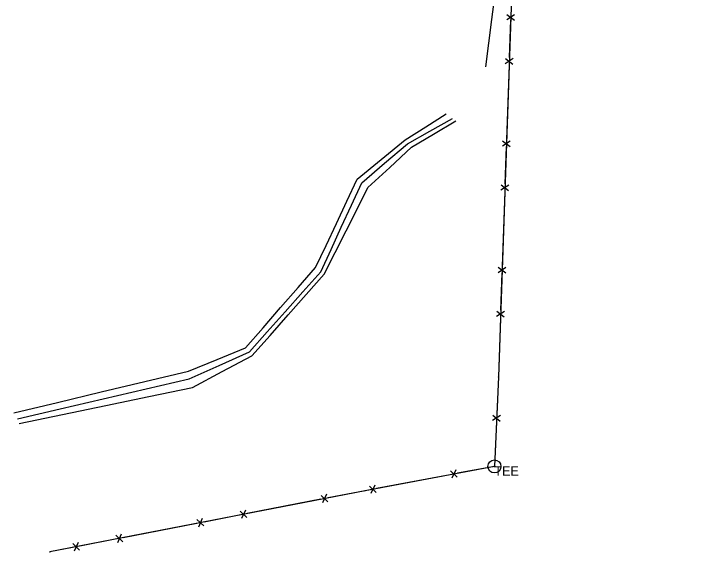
# Model space of a CAD drawing. Extents: x 675481 to 678499, y 212715 to 215285.
# Drawn here: x 676284.7 to 676656.9, y 214248.1 to 214534.9 of the extents above; entities that cross this region are included whole.
import ezdxf

# ---------------------------------------------------------------- set-up
doc = ezdxf.new("R2010")
doc.units = 0
for name, color, linetype in [('S_FENCE', 7, 'Continuous'), ('S_FENCE_ANNOT', 7, 'Continuous'), ('S_MSC_PT_SYM', 7, 'Continuous'), ('S_STREAM', 7, 'Continuous')]:
    doc.layers.add(name, color=color, linetype=linetype)

msp = doc.modelspace()

# ---------------------------------------------------------------- linework, layer by layer
at = {"layer": 'S_FENCE'}
for p, q in [((676554.13, 214666.5), (676542.97, 214341.43)), ((676551.65, 214534.51), (676547.46, 214531.78)), ((676547.55, 214534.65), (676551.55, 214531.64)), ((676550.84, 214511.09), (676546.65, 214508.36)), ((676546.75, 214511.23), (676550.75, 214508.22)), ((676549.33, 214467.11), (676545.14, 214464.39)), ((676545.24, 214467.25), (676549.23, 214464.25)), ((676548.53, 214443.69), (676544.34, 214440.97)), ((676544.44, 214443.83), (676548.43, 214440.83)), ((676547.02, 214399.72), (676542.83, 214396.99)), ((676542.92, 214399.86), (676546.92, 214396.85)), ((676546.21, 214376.3), (676542.02, 214373.57)), ((676542.12, 214376.44), (676546.12, 214373.43)), ((676542.97, 214341.43), (676540.86, 214293.75)), ((676544.11, 214320.8), (676539.89, 214318.12)), ((676540.01, 214320.98), (676543.98, 214317.94)), ((676540.86, 214293.75), (676471.89, 214280.77)), ((676521.03, 214287.93), (676517.45, 214291.43)), ((676520.27, 214291.96), (676518.21, 214287.4)), ((676477.79, 214279.79), (676474.21, 214283.29)), ((676477.03, 214283.82), (676474.97, 214279.26)), ((676471.89, 214280.77), (676303.89, 214248.15)), ((676452.09, 214274.84), (676448.49, 214278.31)), ((676451.31, 214278.86), (676449.27, 214274.29)), ((676408.89, 214266.45), (676405.3, 214269.92)), ((676408.11, 214270.47), (676406.08, 214265.9)), ((676385.89, 214261.98), (676382.29, 214265.46)), ((676385.11, 214266), (676383.07, 214261.44)), ((676342.7, 214253.6), (676339.1, 214257.07)), ((676341.92, 214257.62), (676339.88, 214253.05)), ((676319.69, 214249.13), (676316.1, 214252.61)), ((676318.91, 214253.15), (676316.88, 214248.58))]:
    msp.add_line(p, q, dxfattribs=at)
for points in [[(676549.5, 214531.71), (676548.82, 214511.72)], [(676548.68, 214507.72), (676547.31, 214467.75)], [(676547.19, 214464.32), (676546.5, 214444.33)], [(676546.36, 214440.33), (676544.99, 214400.36)], [(676544.87, 214396.92), (676544.19, 214376.94)], [(676544.05, 214372.94), (676542.97, 214341.43)], [(676542.97, 214341.43), (676542.08, 214321.46)], [(676541.91, 214317.46), (676540.86, 214293.75)], [(676540.86, 214293.75), (676521.21, 214290.05)], [(676517.28, 214289.31), (676477.97, 214281.91)], [(676471.89, 214280.77), (676452.25, 214276.96)], [(676474.59, 214281.28), (676471.89, 214280.77)], [(676448.33, 214276.19), (676409.06, 214268.57)], [(676405.69, 214267.91), (676386.05, 214264.1)], [(676382.13, 214263.34), (676342.86, 214255.72)], [(676339.49, 214255.06), (676319.86, 214251.25)], [(676315.93, 214250.49), (676303.89, 214248.15)]]:
    msp.add_lwpolyline(points, dxfattribs=at)
for radius in [3.49, 0.247, 0.0349]:
    msp.add_circle((676540.86, 214293.75), radius, dxfattribs=at)
at = {"layer": 'S_MSC_PT_SYM'}
for points in [[(676542.97, 214341.43), (676542.97, 214341.48), (676542.97, 214341.43), (676542.92, 214341.43), (676542.97, 214341.43), (676542.97, 214341.38), (676542.97, 214341.43), (676543.02, 214341.43)], [(676540.86, 214293.75), (676540.86, 214293.8), (676540.86, 214293.75), (676540.81, 214293.75), (676540.86, 214293.75), (676540.86, 214293.7), (676540.86, 214293.75), (676540.91, 214293.75)], [(676471.89, 214280.77), (676471.89, 214280.82), (676471.89, 214280.77), (676471.84, 214280.77), (676471.89, 214280.77), (676471.89, 214280.72), (676471.89, 214280.77), (676471.94, 214280.77)], [(676303.89, 214248.15), (676303.89, 214248.2), (676303.89, 214248.15), (676303.84, 214248.15), (676303.89, 214248.15), (676303.89, 214248.1), (676303.89, 214248.15), (676303.94, 214248.15)]]:
    msp.add_lwpolyline(points, dxfattribs=at)
at = {"layer": 'S_STREAM'}
for points in [[(676656.9, 214660.42), (676652.9, 214645.03), (676648.89, 214629.64), (676640.01, 214611.09), (676627.78, 214604.76), (676615.55, 214598.43), (676598.06, 214586.54), (676580.57, 214574.66), (676566.84, 214572.06), (676553.12, 214569.47), (676542.48, 214557.03), (676540.9, 214544.47), (676539.31, 214531.91), (676537.72, 214519.35), (676536.14, 214506.79)], [(676284.71, 214322.27), (676308, 214327.85), (676331.28, 214333.42), (676354.57, 214339), (676377.85, 214344.57), (676393.03, 214350.74), (676408.2, 214356.9), (676417.54, 214367.63), (676426.89, 214378.36), (676436.23, 214389.08), (676445.57, 214399.81), (676451.1, 214411.55), (676456.62, 214423.29), (676462.15, 214435.03), (676467.68, 214446.77), (676480.51, 214457.26), (676493.34, 214467.74), (676504.27, 214474.72), (676515.19, 214481.69)], [(676286.53, 214319.13), (676309.42, 214324.45), (676332.31, 214329.77), (676355.21, 214335.09), (676378.1, 214340.42), (676394.16, 214347.58), (676410.22, 214354.75), (676419.73, 214365.44), (676429.25, 214376.12), (676438.76, 214386.81), (676448.27, 214397.49), (676453.75, 214409.35), (676459.24, 214421.21), (676464.72, 214433.07), (676470.2, 214444.93), (676482.36, 214455.33), (676494.52, 214465.73), (676506.51, 214472.47), (676518.49, 214479.2)], [(676287.41, 214316.61), (676310.51, 214321.41), (676333.61, 214326.21), (676356.71, 214331.01), (676379.82, 214335.82), (676395.69, 214344.26), (676411.57, 214352.71), (676421.23, 214363.58), (676430.88, 214374.45), (676440.53, 214385.32), (676450.19, 214396.19), (676456.01, 214407.72), (676461.83, 214419.26), (676467.65, 214430.79), (676473.47, 214442.33), (676485.03, 214453.14), (676496.59, 214463.95), (676508.44, 214470.9), (676520.29, 214477.86)]]:
    msp.add_lwpolyline(points, dxfattribs=at)

# ---------------------------------------------------------------- texts
at = {"layer": 'S_FENCE_ANNOT'}
msp.add_text('TEE', height=5, dxfattribs=at).set_placement((676540.86, 214288.75))
msp.add_text('TEE', height=5, dxfattribs=at).set_placement((676540.86, 214288.75))

doc.saveas('drawing.dxf')
